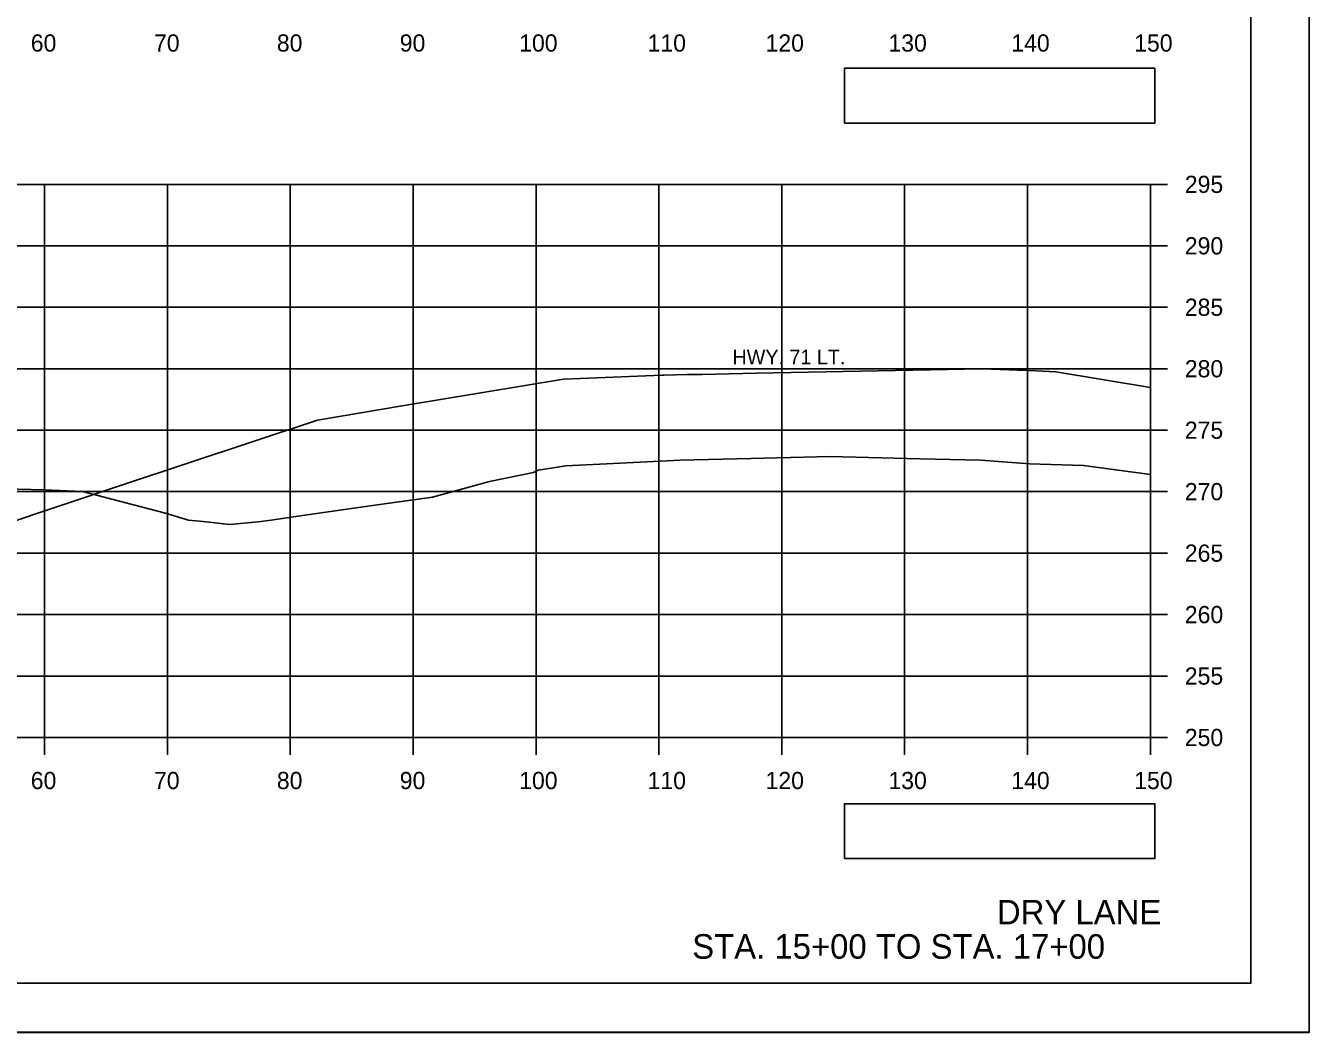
# Model space of a CAD drawing. Extents: x 285 to 4233, y -659 to 3710.
# Drawn here: x 4128.8 to 4233.3, y -152.6 to -70.7 of the extents above; entities that cross this region are included whole.
import ezdxf

# ---------------------------------------------------------------- set-up
doc = ezdxf.new("R2010")
doc.units = 0
for name, color, linetype in [('R_Axis', 7, 'Continuous'), ('R_Axis Annot', 7, 'Continuous'), ('R_Border', 7, 'Continuous'), ('R_Draft', 7, 'Continuous'), ('R_Exist Surface', 7, 'Continuous'), ('R_Fin Surface', 7, 'Continuous'), ('R_Grid', 7, 'Continuous'), ('R_No Plot', 7, 'Continuous'), ('R_Water', 7, 'Continuous')]:
    doc.layers.add(name, color=color, linetype=linetype)

msp = doc.modelspace()

# ---------------------------------------------------------------- linework, layer by layer
at = {"layer": 'R_Axis'}
for p, q in [((4220.38, -128.58), (4220.38, -83.58)), ((4221.78, -83.58), (4220.38, -83.58)), ((4221.78, -88.58), (4220.38, -88.58)), ((4221.78, -93.58), (4220.38, -93.58)), ((4221.78, -98.58), (4220.38, -98.58)), ((4221.78, -103.58), (4220.38, -103.58)), ((4221.78, -108.58), (4220.38, -108.58)), ((4221.78, -113.58), (4220.38, -113.58)), ((4221.78, -118.58), (4220.38, -118.58)), ((4221.78, -123.58), (4220.38, -123.58)), ((3920.38, -128.58), (4220.38, -128.58)), ((4130.38, -129.98), (4130.38, -128.58)), ((4140.38, -129.98), (4140.38, -128.58)), ((4150.38, -129.98), (4150.38, -128.58)), ((4160.38, -129.98), (4160.38, -128.58)), ((4170.38, -129.98), (4170.38, -128.58)), ((4180.38, -129.98), (4180.38, -128.58)), ((4190.38, -129.98), (4190.38, -128.58)), ((4200.38, -129.98), (4200.38, -128.58)), ((4210.38, -129.98), (4210.38, -128.58)), ((4220.38, -129.98), (4220.38, -128.58)), ((4221.78, -128.58), (4220.38, -128.58))]:
    msp.add_line(p, q, dxfattribs=at)
at = {"layer": 'R_Axis Annot'}
for points in [[(4195.48, -78.61), (4220.73, -78.61), (4220.73, -74.14), (4195.48, -74.14)], [(4195.48, -138.43), (4220.73, -138.43), (4220.73, -133.97), (4195.48, -133.97)]]:
    msp.add_lwpolyline(points, close=True, dxfattribs=at)
at = {"layer": 'R_Border'}
for q in [(4228.56, 56.88), (3912.38, -148.58)]:
    msp.add_line((4228.56, -148.58), q, dxfattribs=at)
at = {"layer": 'R_Exist Surface'}
msp.add_lwpolyline([(4109.13, -107.9), (4130.34, -108.43), (4133.46, -108.56), (4140.11, -110.31), (4142.09, -110.9), (4143.29, -111.01), (4145.46, -111.26), (4147.76, -111.03), (4148.83, -110.9), (4151.57, -110.48), (4156.68, -109.77), (4161.95, -109.02), (4166.59, -107.76), (4170.17, -107.03), (4170.28, -106.98), (4170.55, -106.82), (4171.77, -106.64), (4172.81, -106.48), (4177.23, -106.26), (4182.11, -106.01), (4187.87, -105.88), (4194.31, -105.73), (4201.62, -105.9), (4206.59, -106.02), (4208.03, -106.13), (4210.57, -106.31), (4212.27, -106.38), (4214.94, -106.44), (4220.38, -107.18)], dxfattribs=at)
at = {"layer": 'R_Fin Surface'}
msp.add_lwpolyline([(4117.02, -108.1), (4118.7, -108.66), (4126.77, -111.35), (4136.64, -108.06), (4152.59, -102.76), (4159.49, -101.61), (4172.62, -99.42), (4174, -99.37), (4180.64, -99.1), (4180.82, -99.1), (4182.64, -99.06), (4183.91, -99.04), (4188.32, -98.95), (4206.68, -98.58), (4211.06, -98.76), (4212.69, -98.82), (4220.38, -100.1)], dxfattribs=at)
at = {"layer": 'R_Grid'}
for p, q in [((3920.38, -83.58), (4220.38, -83.58)), ((4130.38, -128.58), (4130.38, -83.58)), ((4140.38, -128.58), (4140.38, -83.58)), ((4150.38, -128.58), (4150.38, -83.58)), ((4160.38, -128.58), (4160.38, -83.58)), ((4170.38, -128.58), (4170.38, -83.58)), ((4180.38, -128.58), (4180.38, -83.58)), ((4190.38, -128.58), (4190.38, -83.58)), ((4200.38, -128.58), (4200.38, -83.58)), ((4210.38, -128.58), (4210.38, -83.58)), ((4220.38, -128.58), (4220.38, -83.58)), ((3920.38, -88.58), (4220.38, -88.58)), ((3920.38, -93.58), (4220.38, -93.58)), ((3920.38, -98.58), (4220.38, -98.58)), ((3920.38, -103.58), (4220.38, -103.58)), ((3920.38, -108.58), (4220.38, -108.58)), ((3920.38, -113.58), (4220.38, -113.58)), ((3920.38, -118.58), (4220.38, -118.58)), ((3920.38, -123.58), (4220.38, -123.58)), ((3920.38, -128.58), (4220.38, -128.58))]:
    msp.add_line(p, q, dxfattribs=at)
at = {"layer": 'R_No Plot'}
msp.add_line((3899.98, -152.56), (4233.31, -152.56), dxfattribs=at)
for points in [[(3899.97, 60.77), (4233.31, 60.77), (4233.31, -152.57), (3899.97, -152.57)], [(4146.3, 56.88), (4165.92, 56.88), (4165.92, 47), (4182.03, 47), (4205.23, 47), (4205.35, 18.84), (4228.56, 18.84), (4228.56, -148.58), (3912.38, -148.58), (3912.38, 56.88)]]:
    msp.add_lwpolyline(points, close=True, dxfattribs=at)

# ---------------------------------------------------------------- texts
at = {"layer": 'R_Axis Annot'}
for s, p in [('60', (4129.26, -72.78)), ('70', (4139.29, -72.78)), ('80', (4149.29, -72.78)), ('90', (4159.29, -72.78)), ('100', (4169.01, -72.78)), ('110', (4179.46, -72.78)), ('120', (4189.06, -72.78)), ('130', (4199.06, -72.78)), ('140', (4209.06, -72.78)), ('150', (4219.06, -72.78)), ('295', (4223.18, -84.28)), ('290', (4223.18, -89.28)), ('285', (4223.18, -94.28)), ('280', (4223.18, -99.28)), ('275', (4223.18, -104.28)), ('270', (4223.18, -109.28)), ('265', (4223.18, -114.28)), ('260', (4223.18, -119.28)), ('255', (4223.18, -124.28)), ('250', (4223.18, -129.28)), ('60', (4129.26, -132.78)), ('70', (4139.29, -132.78)), ('80', (4149.29, -132.78)), ('90', (4159.29, -132.78)), ('100', (4169.01, -132.78)), ('110', (4179.46, -132.78)), ('120', (4189.06, -132.78)), ('130', (4199.06, -132.78)), ('140', (4209.06, -132.78)), ('150', (4219.06, -132.78))]:
    msp.add_text(s, height=1.4, dxfattribs=at).set_placement(p)
at = {"layer": 'R_Draft'}
for s, p in [('DRY LANE', (4207.89, -143.79)), ('STA. 15+00 TO STA. 17+00', (4183.09, -146.58))]:
    msp.add_text(s, height=2, dxfattribs=at).set_placement(p)
at = {"layer": 'R_Water'}
msp.add_text('HWY. 71 LT.', height=1.2, dxfattribs=at).set_placement((4186.37, -98.23))

doc.saveas('drawing.dxf')
